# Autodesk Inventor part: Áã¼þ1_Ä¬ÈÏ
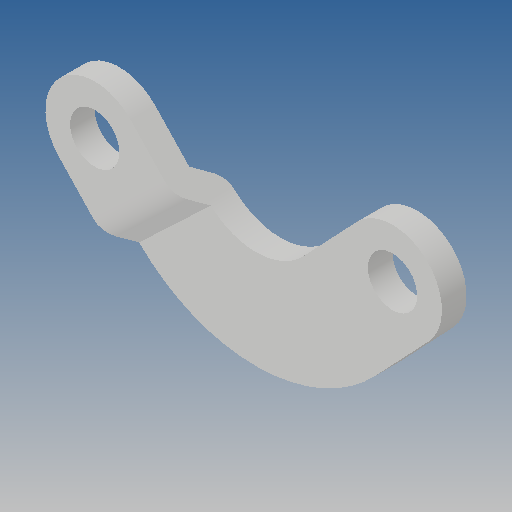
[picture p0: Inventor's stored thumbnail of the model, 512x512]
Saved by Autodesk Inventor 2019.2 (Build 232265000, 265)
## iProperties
Created: 2012-09
Part Number: Áã¼þ1_Ä¬ÈÏ
Material: Ogólny
Document SubType Name: Modeling
Designer: CADENGINEERING4
Density: 1 g/cm^3
Appearance: Domyślna
Author: CADENGINEERING4
Revision Number: ÈÎºÎ
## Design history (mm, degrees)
feature "NONE"
node "Bryła1"
